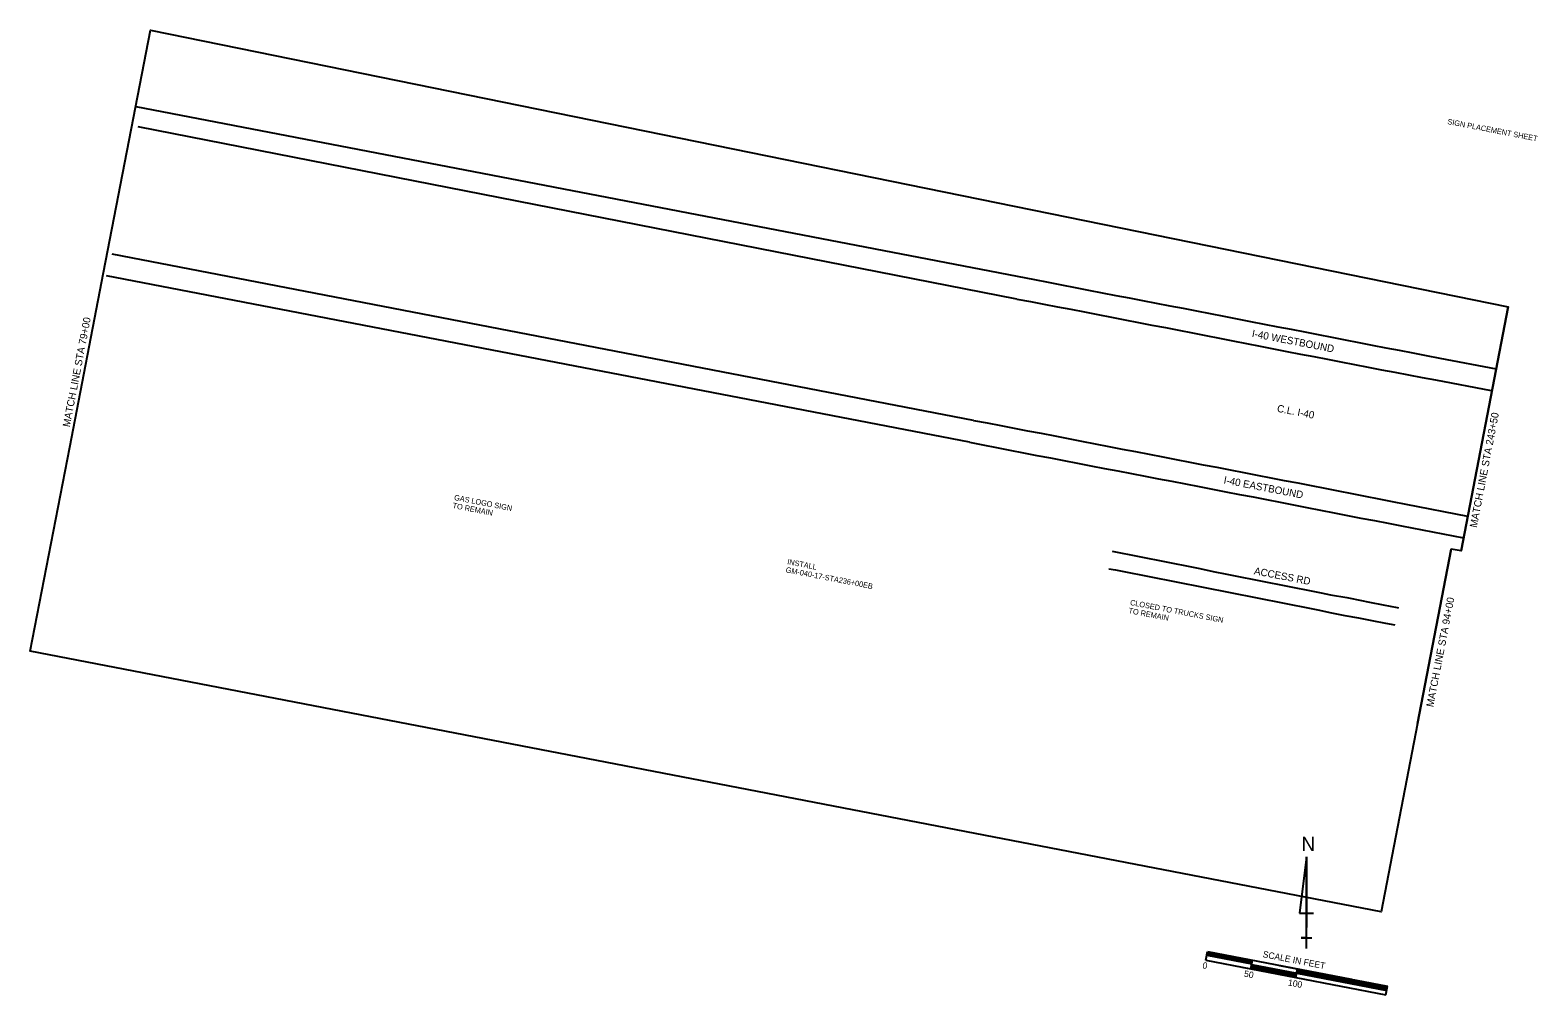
# Model space of a CAD drawing. Extents: x 605579 to 611898, y 415511 to 420658.
# Drawn here: x 605649 to 607293, y 419606 to 420658 of the extents above; entities that cross this region are included whole.
import ezdxf

# ---------------------------------------------------------------- set-up
doc = ezdxf.new("R2010")
doc.units = 0
for name, color, linetype in [('1', 7, 'Continuous'), ('5', 7, 'Continuous'), ('G-ANNO-TEXT', 7, 'Continuous'), ('Level 1', 7, 'Continuous'), ('Level 10', 7, 'Continuous'), ('Plan Notes', 7, 'Continuous'), ('R_Annotation', 7, 'Continuous'), ('R_Draft', 7, 'Continuous')]:
    doc.layers.add(name, color=color, linetype=linetype)

msp = doc.modelspace()

# ---------------------------------------------------------------- linework, layer by layer
at = {"layer": '1'}
msp.add_lwpolyline([(605692.3, 420203.1), (605729, 420393.5), (605780, 420657.7), (607260.6, 420356.1), (607209.2, 420089.7), (607198.5, 420091.8), (607161.7, 419901.4), (607122.1, 419696.1), (605648.9, 419980.5)], close=True, dxfattribs=at)
at = {"layer": '5'}
for p, q in [((605692.3, 420203.1), (605729, 420393.5)), ((607209.2, 420089.7), (607260.6, 420356.1)), ((607161.7, 419901.4), (607198.5, 420091.8))]:
    msp.add_line(p, q, dxfattribs=at)
at = {"layer": 'Level 1'}
for p, q in [((607040.8, 419756.2), (607033.1, 419694.6)), ((607040.8, 419656.2), (607040.8, 419756.2)), ((607040.8, 419756.2), (607040.8, 419679.2)), ((607033.1, 419694.6), (607048.5, 419694.6)), ((607040.8, 419656.2), (607040.8, 419679.2)), ((607040.8, 419667.7), (607035, 419667.7)), ((607035, 419667.7), (607046.6, 419667.7)), ((607040.8, 419656.2), (607040.8, 419667.7))]:
    msp.add_line(p, q, dxfattribs=at)
at = {"layer": 'Level 10'}
for p, q in [((606930.9, 419643.6), (606932.7, 419653)), ((606930.9, 419643.6), (607127.3, 419605.7)), ((606931.9, 419649.1), (606981, 419639.6)), ((606932.1, 419649.9), (606981.2, 419640.4)), ((606932.2, 419650.6), (606981.3, 419641.2)), ((606932.4, 419651.4), (606981.5, 419642)), ((606932.6, 419652.2), (606981.6, 419642.7)), ((606932.7, 419653), (607089.8, 419622.7)), ((606932.7, 419653), (606972, 419645.4)), ((606980, 419634.1), (606981.8, 419643.5)), ((606970.2, 419636), (607009.4, 419628.4)), ((606980.1, 419634.9), (607029.2, 419625.4)), ((606980.3, 419635.7), (607029.4, 419626.2)), ((606980.4, 419636.5), (607029.5, 419627)), ((606980.6, 419637.2), (607029.7, 419627.8)), ((606980.7, 419638), (607029.8, 419628.6)), ((606980.9, 419638.8), (607030, 419629.3)), ((607011.3, 419637.8), (607129.1, 419615.1)), ((607029.1, 419624.6), (607030.9, 419634)), ((607030, 419629.3), (607088.9, 419618)), ((607030, 419629.3), (607128.2, 419610.4)), ((607030.1, 419630.1), (607128.3, 419611.2)), ((607030.3, 419630.9), (607128.5, 419612)), ((607030.4, 419631.7), (607128.6, 419612.7)), ((607030.6, 419632.5), (607128.8, 419613.5)), ((607030.7, 419633.3), (607128.9, 419614.3)), ((607127.3, 419605.6), (607129.1, 419615.1))]:
    msp.add_line(p, q, dxfattribs=at)
at = {"layer": 'R_Draft'}
for p, q in [((606724.9, 420364.5), (605766.5, 420552.2)), ((606677.7, 420232), (605738.2, 420413.3)), ((606673.1, 420208.2), (605732.1, 420389.8))]:
    msp.add_line(p, q, dxfattribs=at)
for points in [[(605764, 420574.6), (606744.2, 420385.6), (606758.9, 420382.7), (606773.6, 420379.9), (606788.4, 420377.1), (606803.1, 420374.2), (606817.8, 420371.4), (606832.6, 420368.5), (606847.3, 420365.7), (606862, 420362.9), (606876.7, 420360), (606891.5, 420357.2), (606906.2, 420354.4), (606920.9, 420351.5), (606935.7, 420348.7), (606950.4, 420345.8), (606965.1, 420342.9), (606979.8, 420340.1), (606994.5, 420337.2), (607009.3, 420334.3), (607024, 420331.5), (607038.7, 420328.6), (607053.4, 420325.7), (607068.2, 420322.9), (607082.9, 420320), (607097.6, 420317.1), (607112.3, 420314.3), (607127.1, 420311.4), (607141.8, 420308.6), (607156.5, 420305.8), (607171.3, 420303), (607186, 420300.1), (607247.5, 420288.3)], [(606724.9, 420364.5), (606739.6, 420361.8), (606754.4, 420359), (606769.1, 420356.1), (606783.8, 420353.3), (606798.5, 420350.4), (606813.3, 420347.5), (606828, 420344.7), (606842.7, 420341.8), (606857.4, 420339), (606872.2, 420336.1), (606886.9, 420333.3), (606901.6, 420330.4), (606916.4, 420327.6), (606931.1, 420324.7), (606945.8, 420321.8), (606960.5, 420318.9), (606975.2, 420316), (606990, 420313.1), (607004.7, 420310.3), (607019.4, 420307.4), (607034.1, 420304.5), (607048.8, 420301.7), (607063.6, 420298.8), (607078.3, 420296), (607093, 420293.1), (607107.8, 420290.3), (607122.5, 420287.4), (607137.2, 420284.6), (607151.9, 420281.8), (607166.7, 420279), (607181.4, 420276.2), (607242, 420264.7)], [(606677.7, 420232), (606692.4, 420229.4), (606707.2, 420226.6), (606721.9, 420223.8), (606736.6, 420220.9), (606751.4, 420218.1), (606766.1, 420215.2), (606780.8, 420212.4), (606795.5, 420209.5), (606810.3, 420206.7), (606825, 420203.8), (606839.7, 420200.9), (606854.4, 420198.1), (606869.2, 420195.2), (606883.9, 420192.3), (606898.6, 420189.5), (606913.3, 420186.7), (606928.1, 420183.8), (606942.8, 420181), (606957.5, 420178.1), (606972.3, 420175.3), (606987, 420172.4), (607001.7, 420169.6), (607016.4, 420166.7), (607031.2, 420163.9), (607045.9, 420161), (607060.6, 420158.1), (607075.3, 420155.3), (607090.1, 420152.4), (607104.8, 420149.5), (607119.5, 420146.6), (607134.2, 420143.7), (607148.9, 420140.9), (607216.3, 420127.7)], [(606673.1, 420208.2), (606687.8, 420205.4), (606702.5, 420202.5), (606717.3, 420199.7), (606732, 420196.9), (606746.7, 420194), (606761.5, 420191.2), (606776.2, 420188.4), (606790.9, 420185.5), (606805.6, 420182.7), (606820.4, 420179.8), (606835.1, 420177), (606849.8, 420174.2), (606864.6, 420171.3), (606879.3, 420168.5), (606894, 420165.7), (606908.7, 420162.8), (606923.5, 420160), (606938.2, 420157.1), (606952.9, 420154.3), (606967.6, 420151.4), (606982.4, 420148.6), (606997.1, 420145.7), (607011.8, 420142.8), (607026.5, 420139.9), (607041.2, 420137.1), (607056, 420134.2), (607070.7, 420131.3), (607085.4, 420128.5), (607100.1, 420125.6), (607114.9, 420122.8), (607129.6, 420119.9), (607144.3, 420117.1), (607211.9, 420104)], [(606828.8, 420089.4), (606836.1, 420088), (606850.8, 420085.1), (606865.6, 420082.3), (606880.3, 420079.4), (606895, 420076.5), (606909.7, 420073.5), (606924.4, 420070.5), (606939.1, 420067.5), (606953.8, 420064.6), (606968.5, 420061.6), (606983.2, 420058.6), (606997.9, 420055.7), (607012.7, 420052.8), (607027.4, 420049.8), (607042.1, 420046.9), (607056.7, 420044), (607066.9, 420042), (607084.6, 420038.9), (607088.3, 420038.1), (607109.3, 420033.9), (607124.4, 420031), (607139.5, 420028.1), (607141.1, 420027.8)], [(606825, 420070.4), (606832.4, 420069), (606847.1, 420066.1), (606861.8, 420063.2), (606876.5, 420060.3), (606891.2, 420057.4), (606906, 420054.6), (606920.7, 420051.7), (606935.4, 420048.8), (606950.1, 420045.8), (606964.8, 420042.9), (606979.5, 420040), (606994.3, 420037.1), (607009, 420034.2), (607023.7, 420031.3), (607038.4, 420028.3), (607053.2, 420025.4), (607067.9, 420022.4), (607082.6, 420019.5), (607097.3, 420016.7), (607112.1, 420013.9), (607126.8, 420011.1), (607137, 420009)]]:
    msp.add_lwpolyline(points, dxfattribs=at)

# ---------------------------------------------------------------- texts
at = {"layer": 'G-ANNO-TEXT'}
msp.add_text('SIGN PLACEMENT SHEET', height=6, rotation=349.0745, dxfattribs=at).set_placement((607194, 420555.3))
at = {"layer": 'Level 1'}
msp.add_text('N', height=15.4, rotation=360, dxfattribs=at).set_placement((607035.2, 419762.6))
at = {"layer": 'Level 10'}
for s, height, p in [('0', 7, (606926.8, 419634.6)), ('SCALE IN FEET', 7.001, (606992.5, 419646.8)), ('50', 7, (606972.1, 419625.6)), ('100', 7, (607020, 419616))]:
    msp.add_text(s, height=height, rotation=349.0748, dxfattribs=at).set_placement(p)
at = {"layer": 'Plan Notes'}
for s, rotation, p in [('MATCH LINE STA 79+00', 79.0745, (605692.1, 420224.4)), ('I-40 WESTBOUND', 349.0745, (606980.7, 420323.3)), ('C.L. I-40', 349.0745, (607008.1, 420241.6)), ('MATCH LINE STA 243+50', 79.0745, (607226.4, 420114.7)), ('I-40 EASTBOUND', 349.0745, (606949.9, 420163.5)), ('ACCESS RD', 349.0745, (606983, 420064.4)), ('MATCH LINE STA 94+00', 79.0745, (607179, 419919))]:
    msp.add_text(s, height=8, rotation=rotation, dxfattribs=at).set_placement(p)
at = {"layer": 'R_Annotation'}
for s, p in [('GAS LOGO SIGN', (606110.8, 420145.4)), ('TO REMAIN', (606109.1, 420136.6)), ('GM-040-17-STA236+00EB', (606472.4, 420066.4)), ('INSTALL', (606474.1, 420075.3)), ('CLOSED TO TRUCKS SIGN', (606847.9, 420030.9)), ('TO REMAIN', (606846.2, 420022))]:
    msp.add_text(s, height=6, rotation=349.0745, dxfattribs=at).set_placement(p)

doc.saveas('drawing.dxf')
